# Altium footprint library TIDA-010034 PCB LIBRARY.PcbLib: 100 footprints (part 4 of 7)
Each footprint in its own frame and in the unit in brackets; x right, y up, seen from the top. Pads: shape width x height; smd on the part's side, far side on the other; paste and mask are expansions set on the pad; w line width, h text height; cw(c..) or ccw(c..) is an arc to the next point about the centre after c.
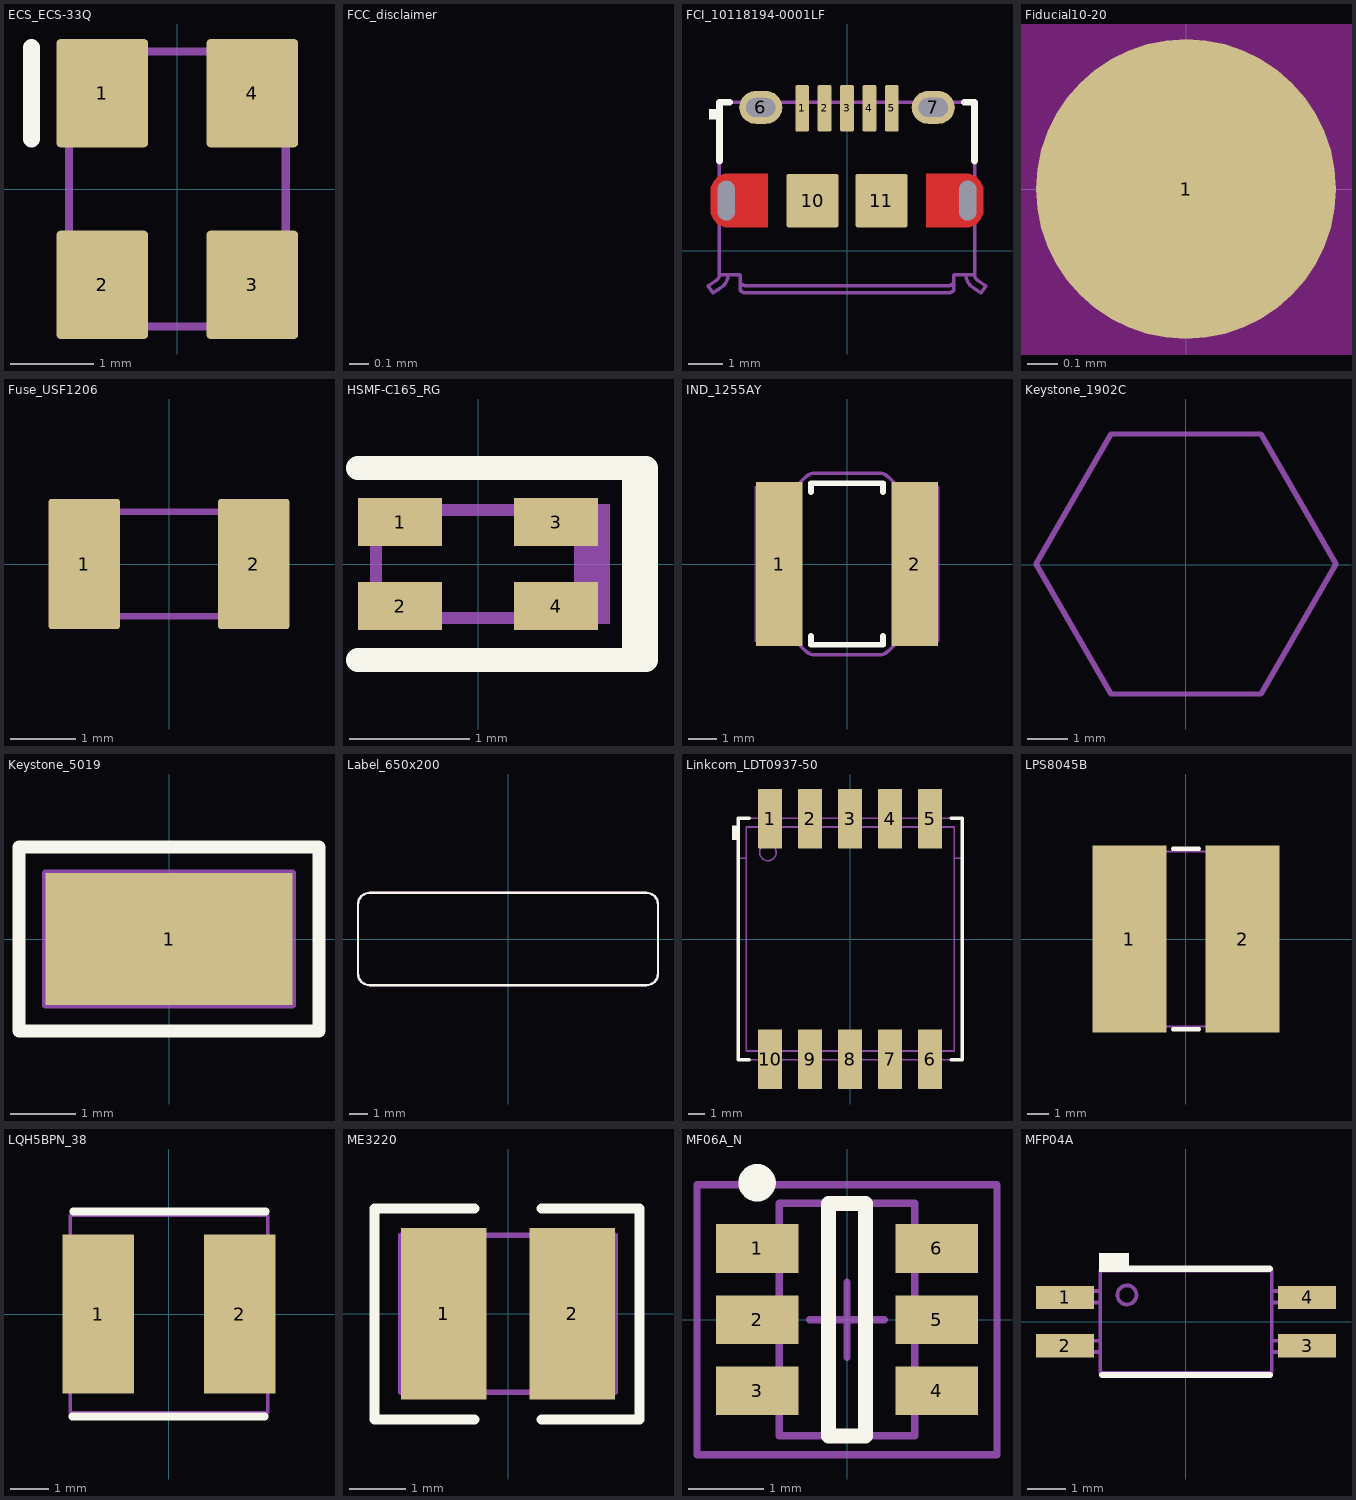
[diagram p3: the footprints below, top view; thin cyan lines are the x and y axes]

## ECS_ECS-33Q [mm] "SMD, 4-Leads, Body 2.5x3.2mm"
height 0.8
pads (4):
  rrect9% 1.1x1.3 smd: 1(-0.9,1.15) 2(-0.9,-1.15) 3(0.9,-1.15) 4(0.9,1.15)
Top Overlay:
  lines w0.2: -1.75,0.6 -1.75,1.7
Mechanical 5:
  circle w0.1: c-0.9,1.2 r0.2
  lines w0.1: -1.3,-1.65 1.3,-1.65 1.3,1.65 -1.3,1.65 -1.3,-1.65
  text ".Designator" at -2.6,-0.4 h0.5
3D body: height 0.8, standoff 0, extent -1.3,-1.65 1.3,1.65
3D body: height 0.81, standoff 0.8, extent -1.099,1.001 -0.701,1.399

## FCC_disclaimer [mm]
Top Overlay:
  text "For evaluation only; not FCC approved for resale." at 23.114,39.624 h1.52

## FCI_10118194-0001LF [mm] "USB-micro B USB 2.0, 0.65mm, 5 Pos, R/A, SMT"
height 3.25
pads (11):
  rrect25% 0.4x1.35 smd: 1(-1.3,4.125) 2(-0.65,4.125) 3(0,4.125) 4(0.65,4.125) 5(1.3,4.125)
  rrect100% 1.25x0.95 hole 0.55 slot 0.85 at 0 deg: 6(-2.5,4.15) 7(2.5,4.15)
  round 0 hole 0.5 slot 1.15 at 90 deg: 8(-3.5,1.45) 9(3.5,1.45)
  rrect7% 1.5x1.55 smd: 10(-1,1.45) 11(1,1.45)
Top Layer:
  region: 3.445,0.675 3.544,0.675 3.728,0.751 3.869,0.892 3.945,1.076 3.945,1.175 3.945,1.725 3.945,1.824 3.869,2.008 3.728,2.149 3.544,2.225 3.445,2.225 2.3,2.225 2.3,0.675
  region: -3.445,0.675 -3.544,0.675 -3.728,0.751 -3.869,0.892 -3.945,1.076 -3.945,1.175 -3.945,1.725 -3.945,1.824 -3.869,2.008 -3.728,2.149 -3.544,2.225 -3.445,2.225 -2.3,2.225 -2.3,0.675
Top Overlay:
  rectangle: -4,3.8 -3.7,4.1
  lines w0.2: -3.7,2.6 -3.7,4.3 -3.4,4.3 ; 3.4,4.3 3.7,4.3 3.7,2.6
Mechanical 5:
  drawing of 446 lines, arcs and shapes, not listed
  text ".Designator" at -2.4,0.6 h1.4
3D body "10118194-0001LF.stp": height 2.72, standoff -0.55, extent -4.025,-1.23 4.025,4.35

## Fiducial10-20 [mm]
pads (1):
  round 1 smd mask+0.5: 1(0,0)
Top Layer keep-out:
  circle w1.178: c0,0 r0.5

## Fuse_USF1206 [mm] "SMD, 2-Leads, Body 3.2x1.6mm"
height 0.6
pads (2):
  rrect9% 1.1x2 smd: 1(-1.3,0) 2(1.3,0)
Mechanical 5:
  lines w0.1: -1.35,-0.8 1.35,-0.8 ; -1.35,-0.8 -1.6,-0.8 -1.6,0.8 -1.35,0.8 ; -1.35,-0.8 -1.35,0.8 ; -1.35,0.8 1.35,0.8 ; 1.35,-0.8 1.6,-0.8 1.6,0.8 1.35,0.8 ; 1.35,-0.8 1.35,0.8
  text ".Designator" at -1,-0.3 h0.55
3D body "3413.0112.24.stp": height 0.65, standoff 0, extent -1.6,-0.8 1.6,0.8

## HSMF-C165_RG [mm] "SMD, 4-Leads, Body 1.6x0.8mm"
height 0.5
pads (4):
  rect 0.7x0.4 smd: 1(-0.65,0.35) 2(-0.65,-0.35) 3(0.65,0.35) 4(0.65,-0.35)
Top Overlay:
  rectangle: 1.2,-0.8 1.5,0.8
  lines w0.2: -1,-0.8 1.4,-0.8 ; -1,0.8 1.4,0.8
Mechanical 5:
  rectangle: 0.85,-0.5 1.1,0.5
  lines w0.1: -0.85,-0.45 -0.85,0.45 0.85,0.45 0.85,-0.45 -0.85,-0.45
  text ".Designator" at -0.7,-0.2 h0.36
3D body: height 0.51, standoff 0.45, extent 0.1,0.1 0.2,0.2
3D body: height 0.51, standoff 0.45, extent -0.2,-0.2 -0.1,-0.1
3D body: height 0.5, standoff 0, extent -0.85,-0.45 0.5,0.45
3D body: height 0.5, standoff 0, extent 0.5,-0.45 0.85,0.45

## IND_1255AY [mm] "Toko DG6045C 1255AY"
height 4.5
pads (2):
  rect 1.6x5.7 smd: 1(-2.35,0) 2(2.35,0)
Top Overlay:
  lines w0.2: -1.25,-2.5 -1.25,-2.8 1.25,-2.8 1.25,-2.5 ; -1.25,2.5 -1.25,2.8 1.25,2.8 1.25,2.5
Mechanical 5:
  lines w0.127: -1.805,-2.65 -3.15,-2.65 -3.15,-1.098 ; -1.805,2.65 -3.15,2.65 -3.15,1.098 ; 1.805,-2.65 3.15,-2.65 3.15,-1.098 ; 1.805,2.65 3.15,2.65 3.15,1.098 ; -3.15,-1.098 ccw(c-2.65,-1.098) -3.004,-1.451 -1.451,-3.004 ccw(c-1.098,-2.65) -1.098,-3.15 1.098,-3.15 ccw(c1.098,-2.65) 1.451,-3.004 3.004,-1.451 ccw(c2.65,-1.098) 3.15,-1.098 ; -3.15,-1.098 -3.15,1.098 ; -3.15,1.098 cw(c-2.65,1.098) -3.004,1.451 -1.451,3.004 cw(c-1.098,2.65) -1.098,3.15 1.098,3.15 cw(c1.098,2.65) 1.451,3.004 3.004,1.451 cw(c2.65,1.098) 3.15,1.098 ; 3.15,-1.098 3.15,1.098
  text ".Designator" at -5.256,-0.855 h1.02
3D body "IND_1255AY.stp": height 4.5, standoff 0, extent -3.15,-3.15 3.15,3.15

## Keystone_1902C [mm] "Hex Standoff, 4-40 threaded, nylon"
height 12.7
Mechanical 5:
  lines w0.127: -3.69,0.012 -1.843,-3.188 1.852,-3.188 3.7,0.012 1.852,3.212 -1.843,3.212 -3.69,0.012
  text ".Designator" at -1.524,-0.508 h1.02
3D body "Keystone_1902C.stp": height 12.73, standoff 0.03, extent -3.682,-3.2 3.708,3.2

## Keystone_5019 [mm] "Test Point, Miniature, SMT"
height 2.29
pads (1):
  rect 3.8x2.03 smd: 1(0,0)
Top Overlay:
  lines w0.2: -2.305,-1.415 2.305,-1.415 2.305,1.415 -2.305,1.415 -2.305,-1.415
Mechanical 5:
  lines w0.1: -1.905,-1.016 1.905,-1.016 1.905,1.016 -1.905,1.016 -1.905,-1.016
  text ".Designator" at -1.725,-0.4 h0.76
3D body "5019.stp": height 2.29, standoff 0, extent -1.905,-1.016 1.905,1.016

## Label_650x200 [mm] "Thermal Transfer Label"
height 0.025
Top Overlay:
  lines w0.127: -8.255,-1.905 ccw(c-7.62,-1.905) -7.62,-2.54 7.62,-2.54 ccw(c7.62,-1.905) 8.255,-1.905 8.255,1.905 ccw(c7.62,1.905) 7.62,2.54 -7.62,2.54 ccw(c-7.62,1.905) -8.255,1.905 -8.255,-1.905
Mechanical 5:
  lines w0.127: -8.255,-1.905 ccw(c-7.62,-1.905) -7.62,-2.54 7.62,-2.54 ccw(c7.62,-1.905) 8.255,-1.905 8.255,1.905 ccw(c7.62,1.905) 7.62,2.54 -7.62,2.54 ccw(c-7.62,1.905) -8.255,1.905 -8.255,-1.905
  text ".Designator" at -1.524,-0.508 h1.02
3D body: height 0.03, standoff 0, extent -8.256,-2.541 8.256,2.541

## Linkcom_LDT0937-50 [mm] "SMD, 10-Leads, Body 14x15.1mm, Pitch 2.5mm"
height 14
pads (10):
  rrect7% 1.5x3.725 smd paste+0: 1(-5,7.512) 2(-2.5,7.512) 3(0,7.512) 4(2.5,7.512) 5(5,7.512) 6(5,-7.512) 7(2.5,-7.512) 8(0,-7.512) 9(-2.5,-7.512) 10(-5,-7.512)
Top Overlay:
  rectangle: -7.4,6.2 -6.9,7.1
  lines w0.2: -7,5.043 -7,-7.55 -6.3,-7.55 ; -7,5.05 -7,7.55 -6.3,7.55 ; 6.3,-7.55 7,-7.55 7,5.043 ; 6.3,7.55 7,7.55 7,5.05
Mechanical 5:
  circle w0.1: c-5.144,5.413 r0.516
  lines w0.1: -6.5,5.043 -7,5.043 -7,-7.55 7,-7.55 7,5.043 6.5,5.043 ; -6.5,5.05 -7,5.05 -7,7.55 7,7.55 7,5.05 6.5,5.05 ; -5.4,-7.55 -5.4,-8.75 -4.6,-8.75 -4.6,-7.55 ; -5.4,7.55 -5.4,8.75 -4.6,8.75 -4.6,7.55 ; -2.9,-7.55 -2.9,-8.75 -2.1,-8.75 -2.1,-7.55 ; -2.9,7.55 -2.9,8.75 -2.1,8.75 -2.1,7.55 ; -0.4,-7.55 -0.4,-8.75 0.4,-8.75 0.4,-7.55 ; -0.4,7.55 -0.4,8.75 0.4,8.75 0.4,7.55 ; 2.1,-7.55 2.1,-8.75 2.9,-8.75 2.9,-7.55 ; 2.1,7.55 2.1,8.75 2.9,8.75 2.9,7.55 ; 4.6,-7.55 4.6,-8.75 5.4,-8.75 5.4,-7.55 ; 4.6,7.55 4.6,8.75 5.4,8.75 5.4,7.55 ; -6.5,-7 6.5,-7 6.5,7 -6.5,7 -6.5,-7
  text ".Designator" at -1.725,-0.35 h1.02
3D body "LDT0939-50.stp": height 14, standoff 0, extent -7,-8.75 7,8.75

## LPS8045B [mm] "COILCRAFT"
height 4.7
pads (2):
  rect 3.4x8.61 smd: 1(-2.605,0) 2(2.605,0)
Top Overlay:
  lines w0.2: -0.6,-4.15 0.6,-4.15 ; -0.6,4.15 0.6,4.15
Mechanical 5:
  lines w0.1: -4.038,-2.962 -2.962,-4.038 2.962,-4.038 4.038,-2.962 4.038,2.962 2.962,4.038 -2.962,4.038 -4.038,2.962 -4.038,-2.962
  text ".Designator" at -1.825,-0.575 h1.02
3D body: height 4.7, standoff 0, extent -4.039,-0.001 4.039,4.039
3D body: height 4.7, standoff 0, extent -4.039,-4.04 4.039,-0.001

## LQH5BPN_38 [mm] "MURATA"
height 4
pads (2):
  rect 1.85x4.1 smd: 1(-1.825,0) 2(1.825,0)
Top Overlay:
  lines w0.2: -2.5,-2.65 2.475,-2.65 ; -2.475,2.65 2.5,2.65
Mechanical 5:
  lines w0.1: -2.55,-2.55 2.55,-2.55 2.55,2.55 -2.55,2.55 -2.55,-2.55
  text ".Designator" at -1.5,-0.5 h1.5
3D body: height 4, standoff 0, extent -2.549,-2.549 2.549,2.549

## ME3220 [mm] "Coilcraft SMT Power Inductor ME3220 inductors"
height 2.4
pads (2):
  rect 1.52x3.05 smd: 1(-1.145,0) 2(1.145,0)
Top Overlay:
  lines w0.178: -2.38,-1.884 -2.38,1.866 ; -2.38,-1.884 -0.6,-1.884 ; -2.38,1.875 -0.6,1.875 ; 0.6,1.878 2.337,1.878 2.337,-1.872 ; 0.6,-1.881 2.337,-1.881
Mechanical 5:
  lines w0.102: -1.905,-1.397 1.905,-1.397 1.905,1.397 -1.905,1.397 -1.905,-1.397
  text ".Designator" at -1.651,-0.508 h0.89
3D body: height 0, standoff 0, extent -1.75,-1.405 1.748,1.403

## MF06A_N [mm] "SOT23, 6-Leads, Body 2.9x1.6mm, Pitch 0.95mm, Lead Span 2.8mm, IPC Medium Density"
height 1.22
pads (6):
  rect 1.1x0.65 smd: 1(-1.2,0.95) 2(-1.2,0) 3(-1.2,-0.95) 4(1.2,-0.95) 5(1.2,0) 6(1.2,0.95)
Top Overlay:
  circle w0.25: c-1.2,1.825 r0.125
  lines w0.2: -0.25,-1.55 0.25,-1.55 0.25,1.55 -0.25,1.55 -0.25,-1.55
Mechanical 5:
  text ".Designator" at -1.524,-0.508 h1.02
Mechanical 13:
  lines w0.1: -0.9,-1.55 -0.9,1.55 0.9,1.55 0.9,-1.55 -0.9,-1.55
Mechanical 15:
  lines w0.1: -0.5,0 0.5,0 ; 0,-0.5 0,0.5 ; -2,-1.8 -2,1.8 2,1.8 2,-1.8 -2,-1.8
3D body: height 1.22, standoff 0, extent -0.9,-1.55 0.9,1.55

## MFP04A [mm] "FAIRCHILD optocoupler"
height 2.39
pads (4):
  rect 1.52x0.61 smd: 1(-3.175,0.635) 2(-3.175,-0.635) 3(3.175,-0.635) 4(3.175,0.635)
Top Overlay:
  rectangle: -2.28,1.3 -1.5,1.8
  lines w0.17: -2.2,-1.4 2.2,-1.4 ; -2.2,1.385 2.2,1.385
Mechanical 5:
  circle w0.1: c-1.55,0.7 r0.25
  lines w0.1: -2.25,-0.8 -3.6,-0.8 -3.6,-0.5 -2.25,-0.5 ; -2.25,0.5 -3.6,0.5 -3.6,0.8 -2.25,0.8 ; 2.25,-0.8 3.6,-0.8 3.6,-0.5 2.25,-0.5 ; 2.25,0.5 3.6,0.5 3.6,0.8 2.25,0.8 ; -2.25,-1.345 2.25,-1.345 2.25,1.345 -2.25,1.345 -2.25,-1.345
  text ".Designator" at -1.9,-0.9 h1.02
3D body: height 2.39, standoff 0, extent -2.249,-1.344 2.249,1.344
3D body: height 1.2, standoff 0, extent -3.599,-0.799 -2.251,-0.501
3D body: height 1.2, standoff 0, extent -3.599,0.501 -2.251,0.799
3D body: height 1.2, standoff 0, extent 2.251,-0.799 3.599,-0.501
3D body: height 1.2, standoff 0, extent 2.251,0.501 3.599,0.799
3D body: height 2.39, standoff 2, extent -1.799,0.451 -1.301,0.949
